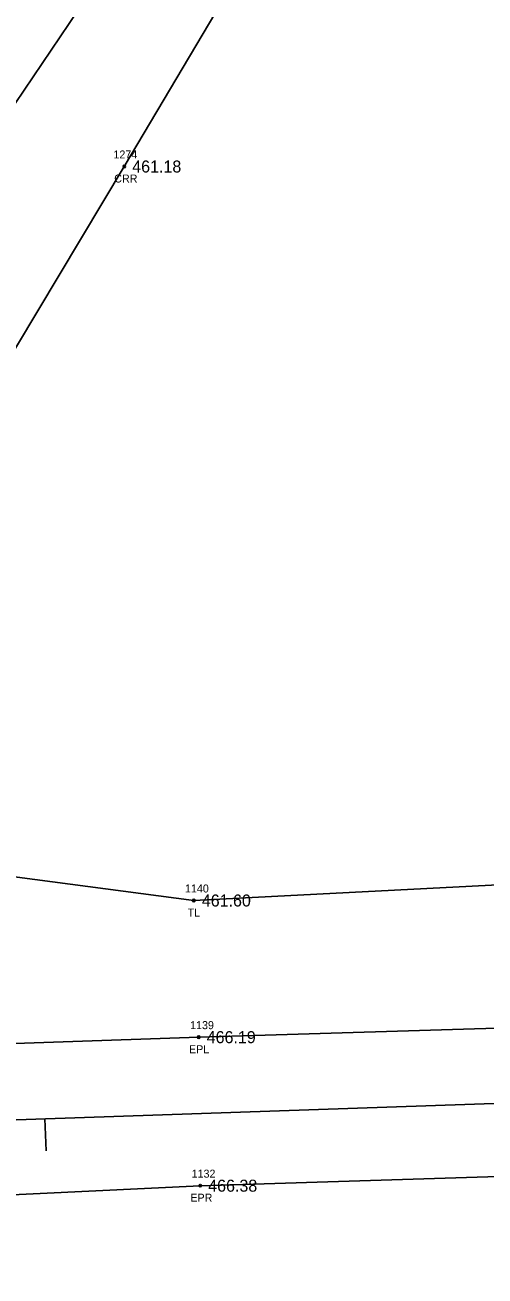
# Model space of a CAD drawing. Extents: x 1784103 to 1787401, y 770251 to 771298.
# Drawn here: x 1785857.4 to 1785914.9, y 770836.9 to 770993.2 of the extents above; entities that cross this region are included whole.
import ezdxf

# ---------------------------------------------------------------- set-up
doc = ezdxf.new("R2010")
doc.units = 0
for name, color, linetype in [('RD_EX_H2O', 7, 'Continuous'), ('RD_EX_H2O_txCode', 7, 'Continuous'), ('RD_EX_Road', 7, 'Continuous'), ('RD_EX_Road_txCode', 7, 'Continuous'), ('RD_EX_TX_H2O_ELEV', 7, 'Continuous'), ('RD_EX_TX_Road_ELEV', 7, 'Continuous'), ('RD_EX_TX_VEG_ELEV', 7, 'Continuous'), ('RD_EX_VEG', 7, 'Continuous'), ('RD_EX_VEG_txCode', 7, 'Continuous'), ('RD_HC_Cl', 7, 'Continuous'), ('RD_HC_Data_Tic', 7, 'Continuous'), ('RD_SMD_Locator', 7, 'Continuous')]:
    doc.layers.add(name, color=color, linetype=linetype)

msp = doc.modelspace()

# ---------------------------------------------------------------- linework, layer by layer
at = {"layer": 'RD_EX_H2O'}
msp.add_lwpolyline([(1785823.91, 770890.02), (1785840.03, 770925.86), (1785869.79, 770975.48), (1785920.39, 771060.62), (1785947.12, 771092.26), (1785958.51, 771131.14), (1785974.06, 771169.93), (1786009.64, 771197.71), (1786027.99, 771233.04), (1786021.73, 771286.51)], dxfattribs=at)
at = {"layer": 'RD_EX_Road'}
for points in [[(1785824.57, 770864.86), (1785879.1, 770866.73), (1785977.08, 770869.67), (1786078.78, 770873.52), (1786179.09, 770876.83), (1786278.08, 770880.28), (1786358.72, 770883.31), (1786381.38, 770883.94), (1786478.25, 770886.75), (1786578.04, 770889.63)], [(1785825.31, 770845.6), (1785879.29, 770848.18), (1785979.17, 770851.29), (1786079.29, 770854.66), (1786178.79, 770858.1), (1786233.56, 770860.16), (1786246.2, 770860.52), (1786278.61, 770861.3), (1786379.15, 770864.94), (1786479.01, 770868.57), (1786578.78, 770871.53)]]:
    msp.add_lwpolyline(points, dxfattribs=at)
at = {"layer": 'RD_EX_VEG'}
msp.add_lwpolyline([(1785221.61, 770869.17), (1785226.44, 770862.44), (1785230.83, 770863.64), (1785281.61, 770865.88), (1785330.18, 770866.95), (1785378.64, 770865.28), (1785481.03, 770871.22), (1785579.9, 770882.43), (1785678.49, 770873.66), (1785753.25, 770880.69), (1785777.57, 770887.66), (1785796.72, 770894.6), (1785878.49, 770883.8), (1786077.63, 770894.05), (1786177.75, 770898.7), (1786232.19, 770912.93), (1786276.99, 770915.77), (1786313.89, 770919.94), (1786357.9, 770947.77)], dxfattribs=at)
at = {"layer": 'RD_HC_Cl'}
for p, q in [((1785851.44, 770976.51), (1785912.04, 771065.72)), ((1787025.56, 770895.93), (1785279.14, 770836.9))]:
    msp.add_line(p, q, dxfattribs=at)
at = {"layer": 'RD_HC_Data_Tic'}
msp.add_line((1785859.87, 770856.53), (1785860.01, 770852.53), dxfattribs=at)
at = {"layer": 'RD_SMD_Locator'}
for centre in [(1785869.79, 770975.48), (1785878.49, 770883.8), (1785879.1, 770866.73), (1785879.29, 770848.18)]:
    msp.add_circle(centre, 0.15, dxfattribs=at)

# ---------------------------------------------------------------- texts
at = {"layer": 'RD_EX_H2O_txCode'}
for s, p in [('1274', (1785868.44, 770976.48)), ('CRR', (1785868.54, 770973.48))]:
    msp.add_text(s, height=1, dxfattribs=at).set_placement(p)
at = {"layer": 'RD_EX_Road_txCode'}
for s, p in [('1139', (1785878.03, 770867.73)), ('EPL', (1785877.89, 770864.73)), ('1132', (1785878.22, 770849.18)), ('EPR', (1785878.06, 770846.18))]:
    msp.add_text(s, height=1, dxfattribs=at).set_placement(p)
at = {"layer": 'RD_EX_TX_H2O_ELEV'}
msp.add_text('461.18', height=1.5, dxfattribs=at).set_placement((1785870.79, 770974.73))
at = {"layer": 'RD_EX_TX_Road_ELEV'}
for s, p in [('466.19', (1785880.1, 770865.98)), ('466.38', (1785880.29, 770847.43))]:
    msp.add_text(s, height=1.5, dxfattribs=at).set_placement(p)
at = {"layer": 'RD_EX_TX_VEG_ELEV'}
msp.add_text('461.60', height=1.5, dxfattribs=at).set_placement((1785879.49, 770883.05))
at = {"layer": 'RD_EX_VEG_txCode'}
for s, p in [('1140', (1785877.39, 770884.8)), ('TL', (1785877.72, 770881.8))]:
    msp.add_text(s, height=1, dxfattribs=at).set_placement(p)

doc.saveas('drawing.dxf')
